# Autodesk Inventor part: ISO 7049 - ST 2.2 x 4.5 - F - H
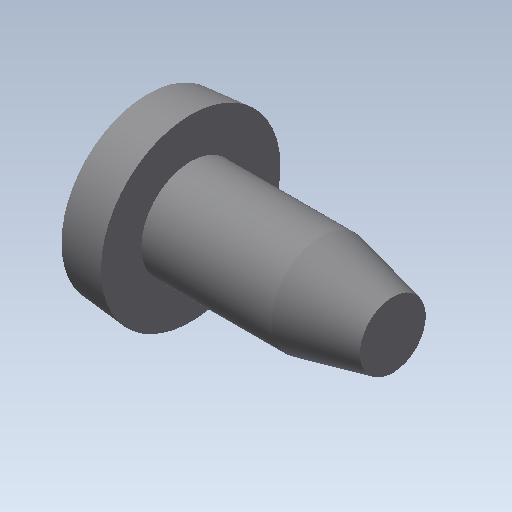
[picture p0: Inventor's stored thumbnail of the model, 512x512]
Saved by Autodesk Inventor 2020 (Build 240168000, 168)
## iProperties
Created: 2002-01
Part Number: ISO 7049 - ST 2.2 x 4.5 - F - H
Material: Générique
Catalog Web Link: file:///C:/Program Files/Autodesk/Inventor 5/Content/Iso/index.htm?doNavigateId=B644153E-6486-4C49-BA92-F814F384E778|E6B68DE9D40241F9B23975AE3FB91F3E|true
Description: Vis à métaux
Document SubType Name: Standard Catalog Part
Standard: ISO 7049 - ST 2.2 x 4.5 - F - H
Designer: Philippe
Density: 1 g/cm^3
Appearance: Par défaut
Shininess: 20.0
Angle Display Precision: 2
Document Length Units: 11269
Document Angle Units: 11279
Document Time Units: 11290
Document Mass Units: 11283
Document Length Units Precision: 3
Document Angle Units Precision: 2
Density: 0.0
Volumn: 0.0
Area: 0.0
PropertySet Name: Model Information
Control State: 0
Master: False
Checked Out: False
Author: Philippe
CLASSIFICATION: 31161506 un/spsc
MANUFACTURER: ISO Système de normes
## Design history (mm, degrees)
feature "Base1"
node "Solide1"
node "Corps solides"
node "Corps surfaciques"
